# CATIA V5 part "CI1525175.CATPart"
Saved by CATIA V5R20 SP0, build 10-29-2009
Part number: CI1525175
Bounding box of the stored display mesh (mm): x -24 to 24, y -19.758 to 209.5, z -29.741 to 27.753
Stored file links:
  C:\Users\Raffaele\Desktop\3D X SITO CF\BOLEX\19-INCLINED ASSEMBLY REF_CI\CI1525175.CATPart

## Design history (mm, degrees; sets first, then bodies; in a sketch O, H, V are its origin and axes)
Set1
  DatumSurface1 to DatumSurface16 "MANIFOLD_SOLID_BREP #393"
  DatumSurface17 to DatumSurface39 "MANIFOLD_SOLID_BREP #1138"
Body1 (main body)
